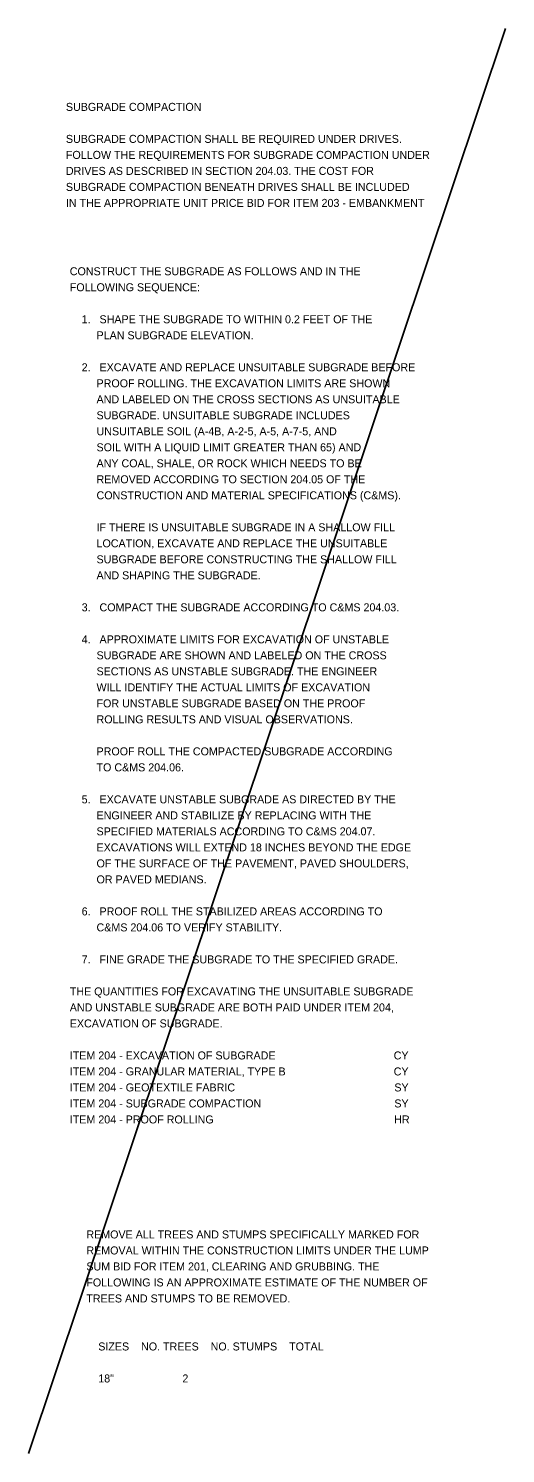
# Model space of a CAD drawing. Extents: x 0 to 76.4, y -34.8 to 22.7.
# Drawn here: x 68.04 to 76.38, y -2.23 to 22.7 of the extents above; entities that cross this region are included whole.
import ezdxf

# ---------------------------------------------------------------- set-up
doc = ezdxf.new("R2010")
doc.units = 0
doc.layers.add('Default', color=7, linetype='Continuous')
doc.layers.add('SH_Text', color=7, linetype='Continuous')

msp = doc.modelspace()

# ---------------------------------------------------------------- linework, layer by layer
at = {"layer": 'Default'}
msp.add_line((76.383, 22.7), (68.038, -2.233), dxfattribs=at)

# ---------------------------------------------------------------- texts
at = {"layer": 'SH_Text'}
for s, p in [('SUBGRADE COMPACTION', (68.692, 21.258)), ('SUBGRADE COMPACTION SHALL BE REQUIRED UNDER DRIVES.', (68.692, 20.698)), ('FOLLOW THE REQUIREMENTS FOR SUBGRADE COMPACTION UNDER', (68.692, 20.418)), ('DRIVES AS DESCRIBED IN SECTION 204.03. THE COST FOR ', (68.692, 20.138)), ('SUBGRADE COMPACTION BENEATH DRIVES SHALL BE INCLUDED ', (68.692, 19.858)), ('IN THE APPROPRIATE UNIT PRICE BID FOR ITEM 203 - EMBANKMENT', (68.692, 19.578)), ('CONSTRUCT THE SUBGRADE AS FOLLOWS AND IN THE', (68.76, 18.382)), ('FOLLOWING SEQUENCE:', (68.76, 18.102)), ('    1.   SHAPE THE SUBGRADE TO WITHIN 0.2 FEET OF THE', (68.76, 17.542)), ('         PLAN SUBGRADE ELEVATION.', (68.76, 17.262)), ('    2.   EXCAVATE AND REPLACE UNSUITABLE SUBGRADE BEFORE', (68.76, 16.702)), ('         PROOF ROLLING. THE EXCAVATION LIMITS ARE SHOWN', (68.76, 16.422)), ('         AND LABELED ON THE CROSS SECTIONS AS UNSUITABLE', (68.76, 16.142)), ('         SUBGRADE. UNSUITABLE SUBGRADE INCLUDES', (68.76, 15.862)), ('         UNSUITABLE SOIL (A-4B, A-2-5, A-5, A-7-5, AND', (68.76, 15.582)), ('         SOIL WITH A LIQUID LIMIT GREATER THAN 65) AND', (68.76, 15.302)), ('         ANY COAL, SHALE, OR ROCK WHICH NEEDS TO BE', (68.76, 15.022)), ('         REMOVED ACCORDING TO SECTION 204.05 OF THE', (68.76, 14.742)), ('         CONSTRUCTION AND MATERIAL SPECIFICATIONS (C&MS).', (68.76, 14.462)), ('         IF THERE IS UNSUITABLE SUBGRADE IN A SHALLOW FILL', (68.76, 13.902)), ('         LOCATION, EXCAVATE AND REPLACE THE UNSUITABLE', (68.76, 13.622)), ('         SUBGRADE BEFORE CONSTRUCTING THE SHALLOW FILL', (68.76, 13.342)), ('         AND SHAPING THE SUBGRADE.', (68.76, 13.062)), ('    3.   COMPACT THE SUBGRADE ACCORDING TO C&MS 204.03.', (68.76, 12.502)), ('    4.   APPROXIMATE LIMITS FOR EXCAVATION OF UNSTABLE', (68.76, 11.942)), ('         SUBGRADE ARE SHOWN AND LABELED ON THE CROSS', (68.76, 11.662)), ('         SECTIONS AS UNSTABLE SUBGRADE. THE ENGINEER', (68.76, 11.382)), ('         WILL IDENTIFY THE ACTUAL LIMITS OF EXCAVATION', (68.76, 11.102)), ('         FOR UNSTABLE SUBGRADE BASED ON THE PROOF', (68.76, 10.822)), ('         ROLLING RESULTS AND VISUAL OBSERVATIONS.', (68.76, 10.542)), ('         PROOF ROLL THE COMPACTED SUBGRADE ACCORDING', (68.76, 9.982)), ('         TO C&MS 204.06.', (68.76, 9.702)), ('    5.   EXCAVATE UNSTABLE SUBGRADE AS DIRECTED BY THE', (68.76, 9.142)), ('         ENGINEER AND STABILIZE BY REPLACING WITH THE', (68.76, 8.862)), ('         SPECIFIED MATERIALS ACCORDING TO C&MS 204.07.', (68.76, 8.582)), ('         EXCAVATIONS WILL EXTEND 18 INCHES BEYOND THE EDGE', (68.76, 8.302)), ('         OF THE SURFACE OF THE PAVEMENT, PAVED SHOULDERS,', (68.76, 8.022)), ('         OR PAVED MEDIANS.', (68.76, 7.742)), ('    6.   PROOF ROLL THE STABILIZED AREAS ACCORDING TO', (68.76, 7.182)), ('         C&MS 204.06 TO VERIFY STABILITY.', (68.76, 6.902)), ('    7.   FINE GRADE THE SUBGRADE TO THE SPECIFIED GRADE.', (68.76, 6.342)), ('THE QUANTITIES FOR EXCAVATING THE UNSUITABLE SUBGRADE', (68.76, 5.782)), ('AND UNSTABLE SUBGRADE ARE BOTH PAID UNDER ITEM 204,', (68.76, 5.502)), ('EXCAVATION OF SUBGRADE.', (68.76, 5.222)), ('ITEM 204 - EXCAVATION OF SUBGRADE', (68.76, 4.662)), ('CY', (74.427, 4.662)), ('ITEM 204 - GRANULAR MATERIAL, TYPE B', (68.76, 4.382)), ('CY', (74.427, 4.382)), ('ITEM 204 - GEOTEXTILE FABRIC', (68.76, 4.102)), ('SY', (74.438, 4.102)), ('ITEM 204 - SUBGRADE COMPACTION', (68.76, 3.822)), ('SY', (74.438, 3.822)), ('ITEM 204 - PROOF ROLLING', (68.76, 3.542)), ('HR', (74.436, 3.542)), ('REMOVE ALL TREES AND STUMPS SPECIFICALLY MARKED FOR', (69.05, 1.53)), ('REMOVAL WITHIN THE CONSTRUCTION LIMITS UNDER THE LUMP', (69.05, 1.25)), ('SUM BID FOR ITEM 201, CLEARING AND GRUBBING. THE', (69.05, 0.97)), ('FOLLOWING IS AN APPROXIMATE ESTIMATE OF THE NUMBER OF', (69.05, 0.69)), ('TREES AND STUMPS TO BE REMOVED.', (69.05, 0.41)), ('    SIZES    NO. TREES    NO. STUMPS    TOTAL', (69.05, -0.43)), ('    18"', (69.05, -0.99)), ('2', (70.73, -0.99))]:
    msp.add_text(s, height=0.14, dxfattribs=at).set_placement(p)

doc.saveas('drawing.dxf')
